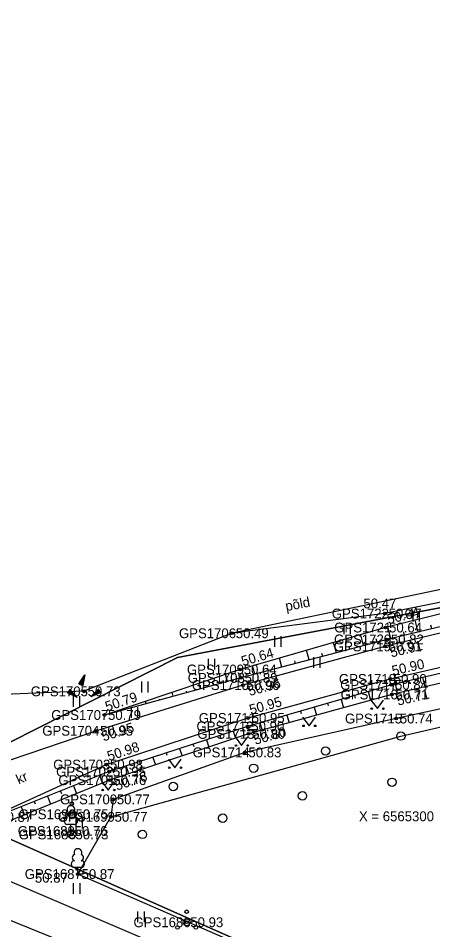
# Model space of a CAD drawing. Extents: x 551623 to 559850, y 6561220 to 6567135.
# Drawn here: x 556218.5 to 556248, y 6565291.9 to 6565356.7 of the extents above; entities that cross this region are included whole.
import ezdxf

# ---------------------------------------------------------------- set-up
doc = ezdxf.new("R2010")
doc.units = 0
for name, color, linetype in [('HALJASTUS', 7, 'Continuous'), ('KORGUS-EH2000', 7, 'Continuous'), ('MOOTKORG-EH2000', 7, 'Continuous'), ('MOOTMPUNKT', 7, 'Continuous'), ('MOOTNR', 7, 'Continuous'), ('MOOTPIIR', 7, 'Continuous'), ('PIIR', 7, 'Continuous'), ('PIIRIMLEITUD', 7, 'Continuous'), ('PUU', 7, 'Continuous'), ('RELJEEF', 7, 'Continuous'), ('TEE', 7, 'Continuous'), ('VORK', 7, 'Continuous')]:
    doc.layers.add(name, color=color, linetype=linetype)

msp = doc.modelspace()

# ---------------------------------------------------------------- linework, layer by layer
at = {"layer": 'HALJASTUS'}
for p, q in [((556246.554, 6565314.564), (556246.554, 6565313.803)), ((556247.01, 6565314.564), (556247.01, 6565313.803)), ((556241.634, 6565313.677), (556241.634, 6565312.916)), ((556242.089, 6565313.677), (556242.089, 6565312.916)), ((556236.718, 6565312.77), (556236.718, 6565312.009)), ((556237.173, 6565312.77), (556237.173, 6565312.009)), ((556231.987, 6565311.154), (556231.987, 6565310.393)), ((556232.442, 6565311.154), (556232.442, 6565310.393)), ((556239.477, 6565311.277), (556239.477, 6565310.516)), ((556239.932, 6565311.277), (556239.932, 6565310.516)), ((556227.255, 6565309.538), (556227.255, 6565308.777)), ((556227.71, 6565309.538), (556227.71, 6565308.777)), ((556222.4, 6565308.509), (556222.4, 6565307.748)), ((556222.855, 6565308.509), (556222.855, 6565307.748)), ((556226.522, 6565307.733), (556226.522, 6565306.972)), ((556226.977, 6565307.733), (556226.977, 6565306.972)), ((556243.563, 6565308.228), (556244.026, 6565307.621)), ((556244.026, 6565307.621), (556244.472, 6565308.228)), ((556238.714, 6565307.008), (556239.177, 6565306.401)), ((556239.177, 6565306.401), (556239.623, 6565307.008)), ((556233.917, 6565305.609), (556234.38, 6565305.003)), ((556234.38, 6565305.003), (556234.826, 6565305.609)), ((556229.174, 6565304.027), (556229.637, 6565303.421)), ((556229.637, 6565303.421), (556230.083, 6565304.027)), ((556224.431, 6565302.445), (556224.894, 6565301.839)), ((556224.894, 6565301.839), (556225.34, 6565302.445)), ((556222.591, 6565299.858), (556222.591, 6565299.096)), ((556223.046, 6565299.858), (556223.046, 6565299.096)), ((556222.411, 6565295.226), (556222.411, 6565294.465)), ((556222.866, 6565295.226), (556222.866, 6565294.465)), ((556226.983, 6565293.203), (556226.983, 6565292.442)), ((556227.438, 6565293.203), (556227.438, 6565292.442))]:
    msp.add_line(p, q, dxfattribs=at)
for points in [[(556292.386, 6565325.238), (556286.728, 6565323.326), (556267.227, 6565318.945), (556244.568, 6565314.375), (556233.701, 6565312.976)], [(556283.768, 6565312.214), (556282.924, 6565313.794), (556268.321, 6565311.876), (556245.361, 6565306.917), (556234.601, 6565304.511), (556225.246, 6565301.174), (556225.084, 6565299.935)]]:
    msp.add_lwpolyline(points, dxfattribs=at)
for centre, radius in [((556243.625, 6565307.621), 0.055), ((556244.454, 6565307.621), 0.055), ((556238.776, 6565306.401), 0.055), ((556239.605, 6565306.401), 0.055), ((556245.706, 6565305.674), 0.3), ((556233.979, 6565305.003), 0.055), ((556234.808, 6565305.003), 0.055), ((556240.35, 6565304.611), 0.3), ((556229.236, 6565303.421), 0.055), ((556230.065, 6565303.421), 0.055), ((556235.229, 6565303.383), 0.3), ((556245.069, 6565302.392), 0.3), ((556224.493, 6565301.839), 0.055), ((556225.322, 6565301.839), 0.055), ((556229.519, 6565302.085), 0.3), ((556238.698, 6565301.424), 0.3), ((556233.035, 6565299.842), 0.3), ((556227.325, 6565298.685), 0.3)]:
    msp.add_circle(centre, radius, dxfattribs=at)
at = {"layer": 'KORGUS-EH2000'}
for centre in [(556244.568, 6565314.375), (556244.6, 6565313.383), (556233.701, 6565312.976), (556244.57, 6565312.043), (556234.267, 6565310.399), (556244.933, 6565309.73), (556234.474, 6565309.292), (556245.054, 6565308.625), (556224.619, 6565307.168), (556234.832, 6565306.956), (556245.361, 6565306.917), (556224.053, 6565306.048), (556234.869, 6565305.826), (556234.601, 6565304.511), (556224.759, 6565303.642), (556224.991, 6565302.538), (556225.084, 6565299.935), (556222.735, 6565295.867)]:
    msp.add_circle(centre, 0.1, dxfattribs=at)
at = {"layer": 'MOOTMPUNKT'}
for centre in [(556244.568, 6565314.375), (556244.6, 6565313.383), (556233.701, 6565312.976), (556244.728, 6565312.537), (556244.57, 6565312.043), (556234.267, 6565310.399), (556234.325, 6565309.803), (556244.933, 6565309.73), (556223.169, 6565308.85), (556234.474, 6565309.292), (556245.025, 6565309.313), (556245.054, 6565308.625), (556224.619, 6565307.168), (556234.832, 6565306.956), (556245.361, 6565306.917), (556234.806, 6565306.359), (556224.053, 6565306.048), (556234.869, 6565305.826), (556234.601, 6565304.511), (556224.759, 6565303.642), (556224.967, 6565303.145), (556224.991, 6565302.538), (556225.246, 6565301.174), (556222.309, 6565300.117), (556225.084, 6565299.935), (556222.24, 6565298.923), (556222.305, 6565298.683), (556222.735, 6565295.867), (556230.469, 6565292.444)]:
    msp.add_circle(centre, 0.1, dxfattribs=at)
at = {"layer": 'MOOTPIIR'}
for points in [[(556317.29, 6565325.671), (556298.007, 6565323.148), (556292.386, 6565325.238), (556233.701, 6565312.976), (556223.169, 6565308.85), (556214.051, 6565308.489), (556203.216, 6565309.397), (556197.609, 6565310.789), (556194.429, 6565307.325), (556191.934, 6565304.799), (556191.351, 6565302.574), (556183.617, 6565304.516), (556162.392, 6565313.566), (556146.837, 6565320.486), (556131.546, 6565328.064), (556116.861, 6565334.423), (556089.682, 6565344.853), (556063.899, 6565353.523), (556057.929, 6565353.821), (556039.198, 6565356.19)], [(556319.439, 6565253.295), (556278.301, 6565271.261), (556258.766, 6565280.179), (556222.735, 6565295.867), (556225.084, 6565299.935), (556245.706, 6565305.674), (556269.066, 6565311.081), (556283.768, 6565312.214), (556299.17, 6565314.853), (556317.928, 6565317.026)]]:
    msp.add_lwpolyline(points, dxfattribs=at)
at = {"layer": 'PIIR'}
for points in [[(556340.11, 6565662.55), (556389.4, 6565609.96), (556364.34, 6565374.53), (556350.73, 6565342.07), (556335.44, 6565331.24), (556229.81, 6565311.25), (556213.87, 6565303.19), (556199.38, 6565295.85), (556122.95, 6565328.71), (556145.23, 6565518.55)], [(556217.39, 6565298.59), (556213.87, 6565303.19), (556229.81, 6565311.25), (556335.44, 6565331.24), (556350.73, 6565342.07), (556507.54, 6565334), (556519.21, 6565368.05), (556548.5, 6565368.1), (556612.15, 6565380.04), (556615.14, 6565380.2), (556613.56, 6565366.23), (556611.32, 6565356.67), (556591.74, 6565273.2), (556570.09, 6565180.67), (556561.87, 6565145.74), (556557.67, 6565147.61), (556393.49, 6565220.36)], [(556206.35, 6565280.04), (556217.39, 6565298.59), (556393.49, 6565220.36), (556274.8, 6564990.28), (556228.34, 6565008.72), (556105.05, 6565057.69), (556140.52, 6565135.89), (556229.38, 6565104.35), (556274.08, 6565194.99), (556184.08, 6565232.1), (556196.52, 6565258.88), (556203.12, 6565272.11)]]:
    msp.add_lwpolyline(points, close=True, dxfattribs=at)
at = {"layer": 'PIIRIMLEITUD'}
msp.add_circle((556222.305, 6565298.683), 0.285, dxfattribs=at)
at = {"layer": 'PUU'}
for p, q in [((556222.48, 6565299.398), (556222, 6565299.398)), ((556222.24, 6565298.923), (556222.24, 6565299.398)), ((556222.62, 6565298.923), (556222.24, 6565298.923)), ((556222.975, 6565296.342), (556222.495, 6565296.342)), ((556222.735, 6565295.867), (556222.735, 6565296.342)), ((556223.115, 6565295.867), (556222.735, 6565295.867))]:
    msp.add_line(p, q, dxfattribs=at)
for centre, radius in [((556222.309, 6565300.867), 0.125), ((556222.309, 6565300.117), 0.25), ((556221.659, 6565299.742), 0.125), ((556222.959, 6565299.742), 0.125), ((556230.469, 6565293.194), 0.125), ((556229.819, 6565292.069), 0.125), ((556230.469, 6565292.444), 0.25), ((556231.119, 6565292.069), 0.125)]:
    msp.add_circle(centre, radius, dxfattribs=at)
for centre, radius, start, end in [((556222.24, 6565300.443), 0.277, 332.5799, 207.4201), ((556222.07, 6565300.096), 0.233, 109.02174, 253.14154), ((556222.41, 6565300.096), 0.233, 286.85082, 70.98591), ((556222.003, 6565299.636), 0.238, 90.0016, 269.3953), ((556222.478, 6565299.636), 0.238, 270.6047, 89.9984), ((556222.735, 6565297.387), 0.277, 332.5799, 207.4201), ((556222.498, 6565296.58), 0.238, 90.0016, 269.3953), ((556222.565, 6565297.04), 0.233, 109.02174, 253.14154), ((556222.906, 6565297.04), 0.233, 286.85082, 70.98591), ((556222.973, 6565296.58), 0.238, 270.6047, 89.9984)]:
    msp.add_arc(centre, radius, start, end, dxfattribs=at)
at = {"layer": 'RELJEEF'}
for p, q in [((556246.928, 6565313.062), (556246.726, 6565313.905)), ((556247.901, 6565313.295), (556247.84, 6565313.55)), ((556243.047, 6565312.095), (556242.842, 6565312.875)), ((556244.983, 6565312.598), (556244.784, 6565313.428)), ((556245.955, 6565312.83), (556245.895, 6565313.081)), ((556241.113, 6565311.587), (556240.92, 6565312.32)), ((556244.014, 6565312.349), (556243.951, 6565312.59)), ((556239.178, 6565311.078), (556238.998, 6565311.765)), ((556240.145, 6565311.332), (556240.089, 6565311.546)), ((556242.08, 6565311.841), (556242.02, 6565312.068)), ((556237.244, 6565310.57), (556237.076, 6565311.21)), ((556238.211, 6565310.824), (556238.159, 6565311.023)), ((556235.31, 6565310.062), (556235.154, 6565310.655)), ((556236.277, 6565310.316), (556236.228, 6565310.501)), ((556222.814, 6565309.376), (556223.234, 6565310.016)), ((556222.914, 6565309.526), (556223.164, 6565309.631)), ((556222.964, 6565309.601), (556223.089, 6565309.656)), ((556223.014, 6565309.676), (556223.184, 6565309.751)), ((556223.064, 6565309.751), (556223.194, 6565309.811)), ((556223.089, 6565309.656), (556223.174, 6565309.691)), ((556223.234, 6565310.016), (556223.094, 6565309.261)), ((556223.109, 6565309.826), (556223.209, 6565309.866)), ((556223.159, 6565309.901), (556223.219, 6565309.926)), ((556223.209, 6565309.976), (556223.229, 6565309.986)), ((556233.377, 6565309.546), (556233.239, 6565310.055)), ((556234.342, 6565309.808), (556234.298, 6565309.978)), ((556246.266, 6565309.602), (556246.312, 6565309.404)), ((556247.24, 6565309.83), (556247.395, 6565309.164)), ((556222.173, 6565308.975), (556221.988, 6565308.735)), ((556222.173, 6565308.975), (556222.678, 6565308.405)), ((556222.173, 6565308.975), (556222.218, 6565308.625)), ((556222.173, 6565308.975), (556222.173, 6565308.975)), ((556222.814, 6565309.376), (556223.139, 6565309.516)), ((556222.814, 6565309.376), (556223.094, 6565309.261)), ((556222.814, 6565309.376), (556222.814, 6565309.376)), ((556222.864, 6565309.451), (556223.149, 6565309.571)), ((556222.879, 6565309.351), (556223.129, 6565309.456)), ((556222.944, 6565309.321), (556223.119, 6565309.396)), ((556223.014, 6565309.296), (556223.109, 6565309.336)), ((556223.079, 6565309.271), (556223.094, 6565309.276)), ((556223.652, 6565308.47), (556224.192, 6565309.015)), ((556224.242, 6565308.94), (556224.142, 6565308.96)), ((556224.202, 6565309), (556224.182, 6565309)), ((556224.362, 6565308.765), (556224.192, 6565309.015)), ((556231.447, 6565309.022), (556231.339, 6565309.419)), ((556232.412, 6565309.284), (556232.375, 6565309.42)), ((556244.328, 6565309.111), (556244.383, 6565308.921)), ((556245.292, 6565309.375), (556245.446, 6565308.715)), ((556222.678, 6565308.405), (556221.988, 6565308.735)), ((556221.998, 6565308.75), (556222.003, 6565308.73)), ((556222.043, 6565308.805), (556222.058, 6565308.705)), ((556222.088, 6565308.865), (556222.113, 6565308.68)), ((556222.128, 6565308.92), (556222.163, 6565308.65)), ((556222.233, 6565308.91), (556222.273, 6565308.6)), ((556222.293, 6565308.84), (556222.328, 6565308.575)), ((556222.353, 6565308.775), (556222.368, 6565308.635)), ((556222.368, 6565308.635), (556222.383, 6565308.545)), ((556222.408, 6565308.705), (556222.438, 6565308.52)), ((556222.468, 6565308.64), (556222.488, 6565308.495)), ((556222.528, 6565308.57), (556222.543, 6565308.47)), ((556222.588, 6565308.505), (556222.598, 6565308.44)), ((556222.648, 6565308.435), (556222.653, 6565308.415)), ((556224.362, 6565308.765), (556223.652, 6565308.47)), ((556223.692, 6565308.485), (556223.677, 6565308.49)), ((556223.777, 6565308.52), (556223.717, 6565308.535)), ((556223.862, 6565308.555), (556223.757, 6565308.575)), ((556223.942, 6565308.59), (556223.802, 6565308.62)), ((556224.027, 6565308.625), (556223.842, 6565308.66)), ((556223.977, 6565308.685), (556223.887, 6565308.705)), ((556224.192, 6565308.695), (556223.927, 6565308.745)), ((556224.277, 6565308.73), (556223.972, 6565308.79)), ((556224.112, 6565308.66), (556223.977, 6565308.685)), ((556224.362, 6565308.765), (556224.012, 6565308.83)), ((556224.322, 6565308.82), (556224.057, 6565308.875)), ((556224.282, 6565308.88), (556224.097, 6565308.915)), ((556224.362, 6565308.765), (556224.362, 6565308.765)), ((556228.552, 6565308.236), (556228.533, 6565308.304)), ((556229.517, 6565308.498), (556229.44, 6565308.782)), ((556230.482, 6565308.76), (556230.454, 6565308.862)), ((556242.406, 6565308.556), (556242.459, 6565308.373)), ((556243.367, 6565308.834), (556243.547, 6565308.211)), ((556226.622, 6565307.712), (556226.612, 6565307.747)), ((556227.587, 6565307.974), (556227.54, 6565308.146)), ((556239.524, 6565307.723), (556239.69, 6565307.151)), ((556240.485, 6565308.001), (556240.536, 6565307.825)), ((556241.446, 6565308.278), (556241.618, 6565307.681)), ((556224.692, 6565307.188), (556224.691, 6565307.189)), ((556225.657, 6565307.45), (556225.64, 6565307.51)), ((556237.603, 6565307.168), (556237.761, 6565306.621)), ((556238.564, 6565307.445), (556238.612, 6565307.278)), ((556235.682, 6565306.612), (556235.832, 6565306.091)), ((556236.642, 6565306.89), (556236.689, 6565306.73)), ((556232.821, 6565305.711), (556232.871, 6565305.557)), ((556233.771, 6565306.021), (556233.936, 6565305.516)), ((556234.722, 6565306.332), (556234.771, 6565306.181)), ((556230.92, 6565305.09), (556230.971, 6565304.933)), ((556231.87, 6565305.4), (556232.039, 6565304.884)), ((556229.018, 6565304.469), (556229.071, 6565304.309)), ((556229.969, 6565304.779), (556230.141, 6565304.253)), ((556227.117, 6565303.848), (556227.171, 6565303.685)), ((556228.068, 6565304.158), (556228.243, 6565303.621)), ((556225.216, 6565303.227), (556225.27, 6565303.061)), ((556226.167, 6565303.537), (556226.346, 6565302.989)), ((556223.353, 6565302.502), (556223.418, 6565302.339)), ((556224.282, 6565302.872), (556224.495, 6565302.337)), ((556222.424, 6565302.131), (556222.642, 6565301.583)), ((556220.566, 6565301.39), (556220.79, 6565300.83)), ((556221.495, 6565301.761), (556221.561, 6565301.594)), ((556218.708, 6565300.65), (556218.937, 6565300.076)), ((556219.637, 6565301.02), (556219.705, 6565300.85))]:
    msp.add_line(p, q, dxfattribs=at)
for points in [[(556297.741, 6565324.073), (556286.631, 6565321.814), (556267.416, 6565317.958), (556244.728, 6565312.537), (556234.325, 6565309.803), (556224.619, 6565307.168)], [(556297.741, 6565324.073), (556286.693, 6565322.639), (556267.227, 6565318.945), (556244.6, 6565313.383), (556234.267, 6565310.399), (556224.619, 6565307.168)], [(556298.237, 6565319.643), (556286.954, 6565318.548), (556267.873, 6565314.642), (556245.025, 6565309.313), (556234.806, 6565306.359), (556224.967, 6565303.145), (556216.887, 6565299.924), (556215.839, 6565298.816)], [(556298.237, 6565319.643), (556286.916, 6565317.511), (556268.077, 6565313.926), (556245.054, 6565308.625), (556234.869, 6565305.826), (556224.991, 6565302.538), (556215.839, 6565298.816)]]:
    msp.add_lwpolyline(points, dxfattribs=at)
at = {"layer": 'TEE'}
for points in [[(556356.597, 6565346.303), (556351.215, 6565339.154), (556344.863, 6565333.835), (556337.149, 6565329.848), (556328.266, 6565327.228), (556317.29, 6565325.671), (556298.007, 6565323.148), (556286.58, 6565321.39), (556267.546, 6565317.57), (556244.57, 6565312.043), (556234.474, 6565309.292), (556224.053, 6565306.048), (556211.7, 6565301.845), (556209.919, 6565301.461), (556206.606, 6565301.399), (556202.993, 6565302.377), (556199.245, 6565304.369), (556194.429, 6565307.325)], [(556175.15, 6565203.291), (556172.371, 6565205.166), (556170.617, 6565207.184), (556180.061, 6565228.987), (556188.487, 6565247.314), (556199.182, 6565269.439), (556203.276, 6565278.708), (556205.245, 6565285.017), (556206.201, 6565290.125), (556208.027, 6565293.465), (556209.59, 6565295.964), (556212.519, 6565297.656), (556212.957, 6565298.286), (556224.759, 6565303.642), (556234.832, 6565306.956), (556244.933, 6565309.73), (556267.841, 6565315.013), (556286.927, 6565318.955), (556298.088, 6565320.723), (556317.752, 6565323.201)], [(556212.519, 6565297.656), (556233.204, 6565288.814), (556257.431, 6565277.885), (556277.379, 6565268.878), (556295.258, 6565260.972), (556307.223, 6565255.623), (556319.32, 6565250.223), (556331.627, 6565244.871), (556340.735, 6565240.974), (556360.587, 6565232.345), (556381.381, 6565222.917), (556405.852, 6565212.41), (556418.096, 6565207.028), (556442.438, 6565196.365)], [(556563.777, 6565138.667), (556560.868, 6565140.849), (556553.174, 6565143.6), (556545.589, 6565147.013), (556535.182, 6565151.57), (556522.842, 6565156.959), (556502.184, 6565166.778), (556486.192, 6565174.091), (556471.011, 6565180.892), (556450.062, 6565190.454), (556440.995, 6565194.267), (556416.948, 6565204.811), (556405, 6565210.263), (556380.262, 6565220.954), (556359.747, 6565229.991), (556339.784, 6565238.7), (556330.661, 6565242.666), (556318.495, 6565248.069), (556305.998, 6565253.52), (556294.082, 6565258.94), (556276.195, 6565266.757), (556256.289, 6565275.582), (556232.166, 6565286.787), (556209.59, 6565295.964)]]:
    msp.add_lwpolyline(points, dxfattribs=at)

# ---------------------------------------------------------------- texts
at = {"layer": 'HALJASTUS'}
msp.add_text('põld', height=0.7, rotation=11.07695, dxfattribs=at).set_placement((556237.556, 6565314.543))
at = {"layer": 'KORGUS-EH2000'}
for s, p in [(' 50.47', (556242.778, 6565314.744)), (' 50.49', (556233.701, 6565312.626)), (' 50.74', (556245.361, 6565306.567)), (' 50.83', (556234.601, 6565304.161)), (' 50.77', (556225.084, 6565299.586)), (' 50.87', (556219.421, 6565295.256))]:
    msp.add_text(s, height=0.7, dxfattribs=at).set_placement(p)
for s, rotation, p in [(' 50.64', 13.81104, (556244.559, 6565313.553)), (' 50.91', 13.52557, (556244.775, 6565311.193)), (' 50.64', 16.10593, (556234.218, 6565310.567)), (' 50.90', 12.98786, (556244.893, 6565309.9)), (' 50.96', 15.24623, (556234.704, 6565308.447)), (' 50.71', 12.96608, (556245.251, 6565307.773)), (' 50.79', 18.51616, (556224.564, 6565307.334)), (' 50.95', 15.35256, (556234.786, 6565307.125)), (' 50.95', 17.28695, (556224.313, 6565305.213)), (' 50.80', 15.36625, (556235.101, 6565304.982)), (' 50.98', 18.21231, (556224.705, 6565303.809)), (' 50.76', 18.40971, (556225.267, 6565301.708))]:
    msp.add_text(s, height=0.7, rotation=rotation, dxfattribs=at).set_placement(p)
at = {"layer": 'MOOTKORG-EH2000'}
for s, p in [(' 50.47', (556244.568, 6565314.025)), (' 50.64', (556244.6, 6565313.033)), (' 50.49', (556233.701, 6565312.626)), (' 50.82', (556244.728, 6565312.187)), (' 50.91', (556244.57, 6565311.693)), (' 50.64', (556234.267, 6565310.049)), (' 50.89', (556234.325, 6565309.453)), (' 50.96', (556234.474, 6565308.941)), (' 50.90', (556244.933, 6565309.38)), (' 50.84', (556245.025, 6565308.963)), (' 50.73', (556223.169, 6565308.5)), (' 50.71', (556245.054, 6565308.275)), (' 50.79', (556224.619, 6565306.818)), (' 50.95', (556234.832, 6565306.606)), (' 50.74', (556245.361, 6565306.567)), (' 50.95', (556224.053, 6565305.698)), (' 50.90', (556234.806, 6565306.009)), (' 50.80', (556234.869, 6565305.476)), (' 50.83', (556234.601, 6565304.161)), (' 50.98', (556224.759, 6565303.292)), (' 50.95', (556224.967, 6565302.795)), (' 50.76', (556224.991, 6565302.188)), (' 50.77', (556225.246, 6565300.824)), (' 50.87', (556216.887, 6565299.574)), (' 50.75', (556222.309, 6565299.767)), (' 50.77', (556225.084, 6565299.586)), (' 50.76', (556222.24, 6565298.573)), (' 50.73', (556222.305, 6565298.333)), (' 50.87', (556222.735, 6565295.517)), (' 50.93', (556230.469, 6565292.094))]:
    msp.add_text(s, height=0.7, dxfattribs=at).set_placement(p)
at = {"layer": 'MOOTNR'}
for s, p in [('GPS1722 ', (556240.788, 6565314.025)), ('GPS1721 ', (556240.961, 6565313.033)), ('GPS1706 ', (556229.921, 6565312.626)), ('GPS1720 ', (556240.948, 6565312.187)), ('GPS1719 ', (556240.931, 6565311.693)), ('GPS1709 ', (556230.487, 6565310.049)), ('GPS1708 ', (556230.545, 6565309.453)), ('GPS1710 ', (556230.834, 6565308.941)), ('GPS1718 ', (556241.293, 6565309.38)), ('GPS1717 ', (556241.385, 6565308.963)), ('GPS1705 ', (556219.389, 6565308.5)), ('GPS1716 ', (556241.415, 6565308.275)), ('GPS1707 ', (556220.84, 6565306.818)), ('GPS1711 ', (556231.332, 6565306.606)), ('GPS1715 ', (556241.721, 6565306.567)), ('GPS1704 ', (556220.203, 6565305.698)), ('GPS1712 ', (556231.166, 6565306.009)), ('GPS1713 ', (556231.229, 6565305.476)), ('GPS1714 ', (556230.892, 6565304.161)), ('GPS1703 ', (556220.98, 6565303.292)), ('GPS1702 ', (556221.187, 6565302.795)), ('GPS1701 ', (556221.351, 6565302.188)), ('GPS1700 ', (556221.466, 6565300.824)), ('GPS1690 ', (556218.529, 6565299.767)), ('GPS1699 ', (556221.305, 6565299.586)), ('GPS1689 ', (556218.46, 6565298.573)), ('GPS1688 ', (556218.525, 6565298.333)), ('GPS1687 ', (556218.956, 6565295.517)), ('GPS1686 ', (556226.689, 6565292.094))]:
    msp.add_text(s, height=0.7, dxfattribs=at).set_placement(p)
at = {"layer": 'TEE'}
msp.add_text('kr', height=0.7, rotation=24.59151, dxfattribs=at).set_placement((556218.536, 6565302.23))
at = {"layer": 'VORK'}
msp.add_text('X = 6565300', height=0.7, dxfattribs=at).set_placement((556242.719, 6565299.621))

doc.saveas('drawing.dxf')
